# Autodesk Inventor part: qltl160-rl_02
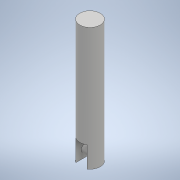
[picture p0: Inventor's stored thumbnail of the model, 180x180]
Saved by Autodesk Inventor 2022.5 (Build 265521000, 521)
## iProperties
Part Number: qltl160-rl_02
Material: 一般
Document SubType Name: Modeling
Designer: ImaoCorp
Density: 1 g/cm^3
Appearance: 既定
Author: ImaoCorp
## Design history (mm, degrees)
feature "qltl160-rl_02"
node "ソリッド1"
